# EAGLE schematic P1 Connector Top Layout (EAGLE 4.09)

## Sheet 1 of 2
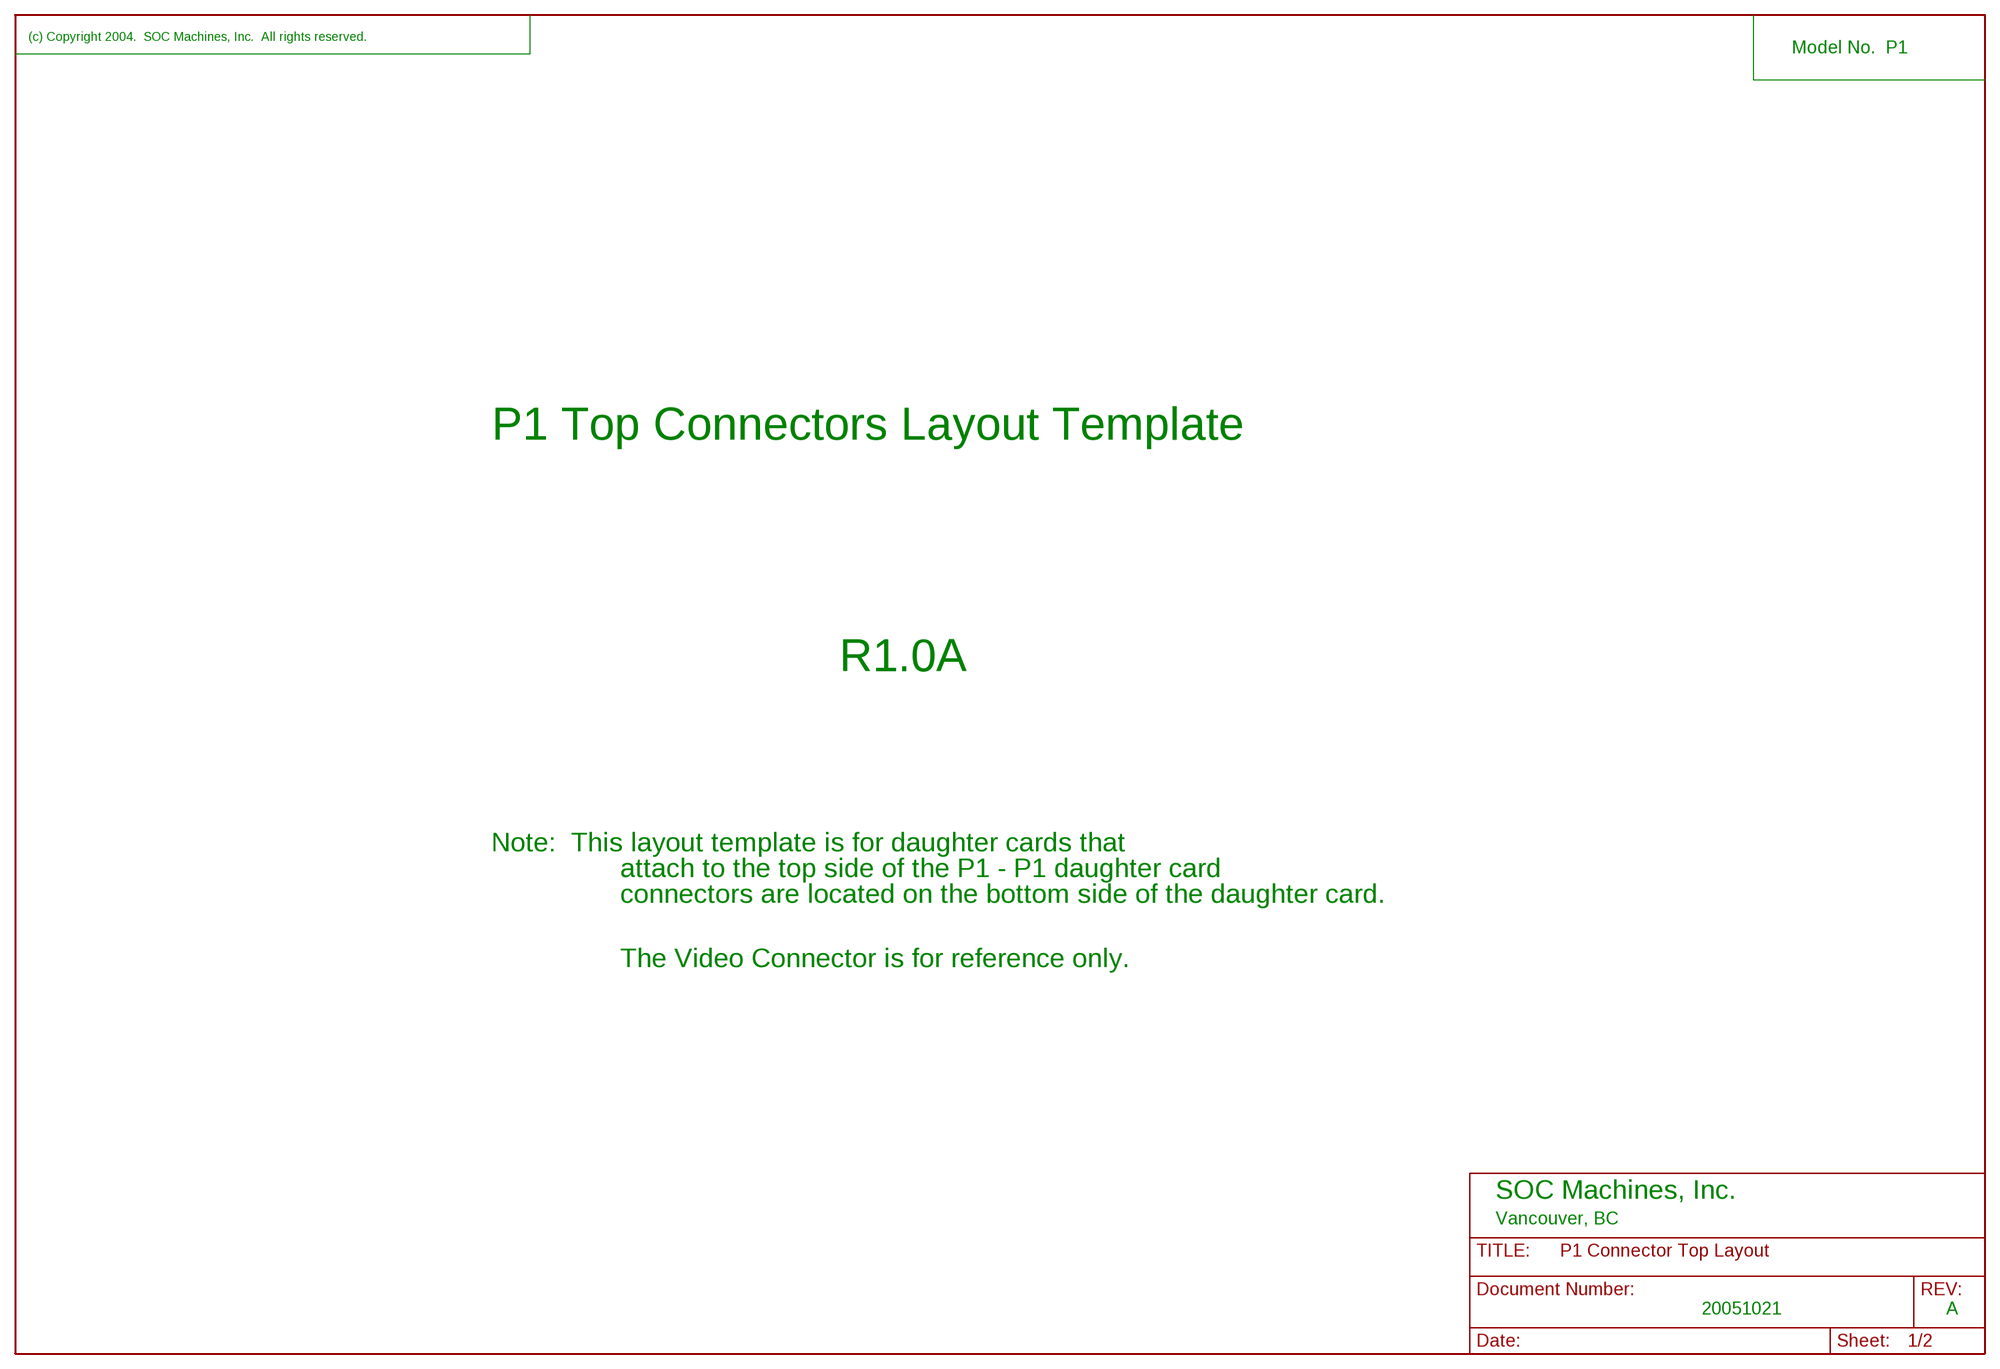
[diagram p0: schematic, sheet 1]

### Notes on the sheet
- (c) Copyright 2004.  SOC Machines, Inc.  All rights reserved.
- Model No.  P1
- P1 Top Connectors Layout Template
- R1.0A
- Note:  This layout template is for daughter cards that
- attach to the top side of the P1 - P1 daughter card
- connectors are located on the bottom side of the daughter card.
- The Video Connector is for reference only.
- SOC Machines, Inc.
- Vancouver, BC
- 20051021 | A

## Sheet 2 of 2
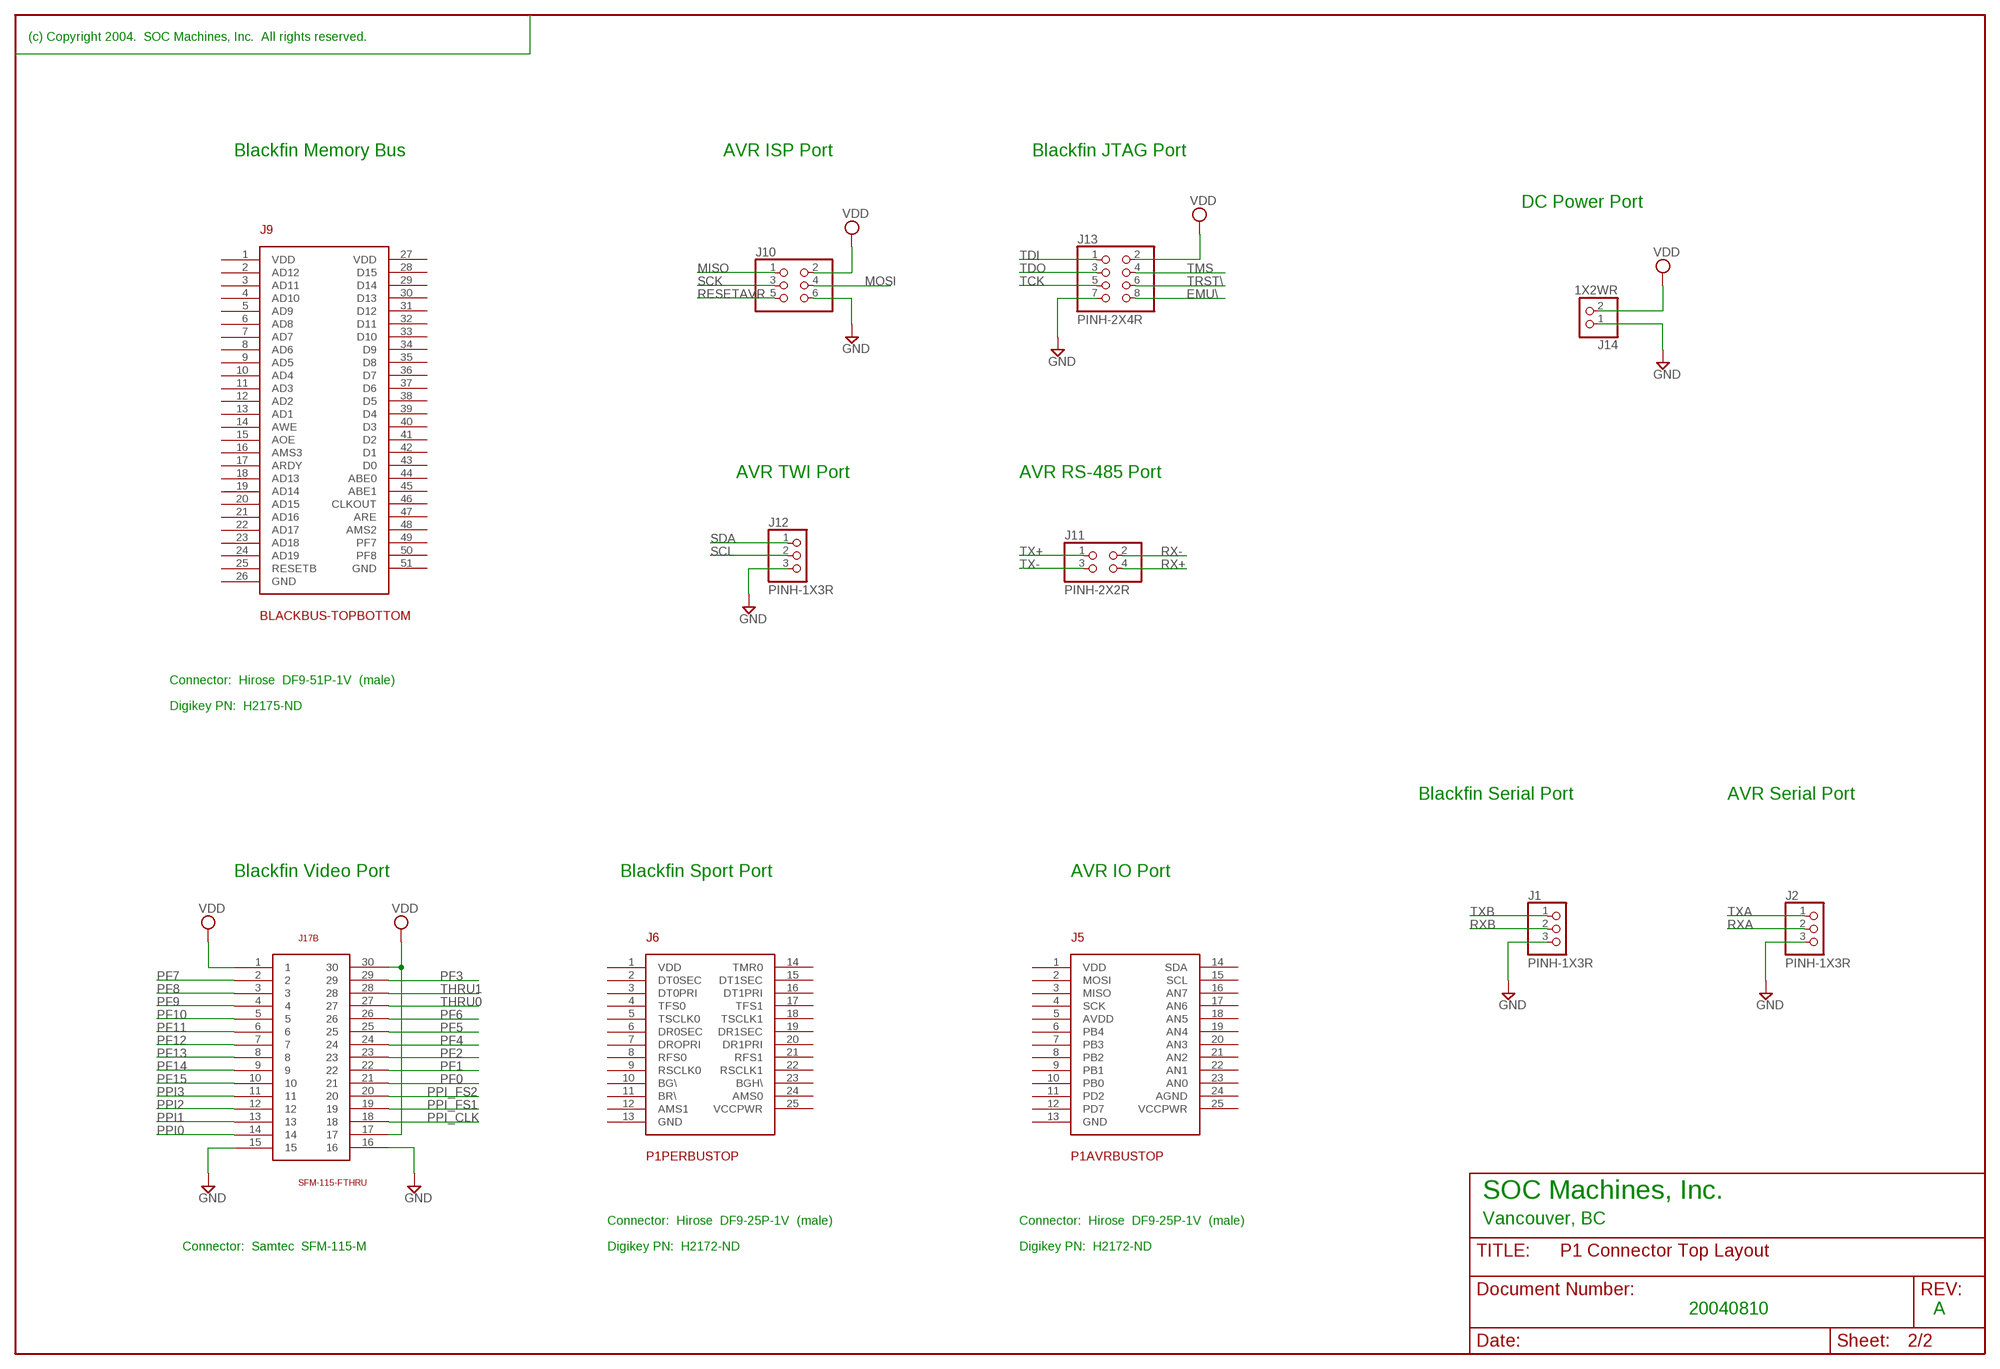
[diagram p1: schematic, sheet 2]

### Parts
J1  PINH-1X3R  [1X3ROUND]
J2  PINH-1X3R  [1X3ROUND]
J5  P1AVRBUSTOP  [DF9-25S]
J6  P1PERBUSTOP  [DF9-25S]
J9  BLACKBUS-TOPBOTTOM  [DF9P-1V]
J10  PINHD-2X3  [2X03]
J11  PINH-2X2R  [2X2ROUND]
J12  PINH-1X3R  [1X3ROUND]
J13  PINH-2X4R  [2X4ROUND]
J14  1X2WR  [1X2WROUND]
J17B  SFM-115-FTHRU  [SFM-115-F]

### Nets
EMU\: J13.8
GND: J1.3 J2.3 J10.6 J12.3 J13.7 J14.1 J17B.15 J17B.16
MISO: J10.1
MOSI: J10.4
PF0: J17B.21
PF1: J17B.22
PF2: J17B.23
PF3: J17B.29
PF4: J17B.24
PF5: J17B.25
PF6: J17B.26
PF7: J17B.2
PF8: J17B.3
PF9: J17B.4
PF10: J17B.5
PF11: J17B.6
PF12: J17B.7
PF13: J17B.8
PF14: J17B.9
PF15: J17B.10
PPI0: J17B.14
PPI1: J17B.13
PPI2: J17B.12
PPI3: J17B.11
PPI_CLK: J17B.18
PPI_FS1: J17B.19
PPI_FS2: J17B.20
RESETAVR: J10.5
RX+: J11.4
RX-: J11.2
RXA: J2.2
RXB: J1.2
SCK: J10.3
SCL: J12.2
SDA: J12.1
TCK: J13.5
TDI: J13.1
TDO: J13.3
THRU0: J17B.27
THRU1: J17B.28
TMS: J13.4
TRST\: J13.6
TX+: J11.1
TX-: J11.3
TXA: J2.1
TXB: J1.1
VDD: J10.2 J13.2 J14.2 J17B.1 J17B.17 J17B.30
Unconnected: J5.2(MOSI) J5.3(MISO) J5.4(SCK) J5.6(PB4) J5.7(PB3) J5.8(PB2) J5.9(PB1) J5.10(PB0) J5.11(PD2) J5.12(PD7) J5.14(SDA) J5.15(SCL) J5.16(AN7) J5.17(AN6) J5.18(AN5) J5.19(AN4) J5.20(AN3) J5.21(AN2) J5.22(AN1) J5.23(AN0) J5.25(VCCPWR) J6.2(DT0SEC) J6.3(DT0PRI) J6.4(TFS0) J6.5(TSCLK0) J6.6(DR0SEC) J6.7(DROPRI) J6.8(RFS0) J6.9(RSCLK0) J6.10(BG\) J6.11(BR\) J6.12(AMS1) J6.14(TMR0) J6.15(DT1SEC) J6.16(DT1PRI) J6.17(TFS1) J6.18(TSCLK1) J6.19(DR1SEC) J6.20(DR1PRI) J6.21(RFS1) J6.22(RSCLK1) J6.23(BGH\) J6.24(AMS0) J9.2(AD12) J9.3(AD11) J9.4(AD10) J9.5(AD9) J9.6(AD8) J9.7(AD7) J9.8(AD6) J9.9(AD5) J9.10(AD4) J9.11(AD3) J9.12(AD2) J9.13(AD1) J9.14(AWE) J9.15(AOE) J9.16(AMS3) J9.17(ARDY) J9.18(AD13) J9.19(AD14) J9.20(AD15) J9.21(AD16) J9.22(AD17) J9.23(AD18) J9.24(AD19) J9.25(RESETB) J9.28(D15) J9.29(D14) J9.30(D13) J9.31(D12) J9.32(D11) J9.33(D10) J9.34(D9) J9.35(D8) J9.36(D7) J9.37(D6) J9.38(D5) J9.39(D4) J9.40(D3) J9.41(D2) J9.42(D1) J9.43(D0) J9.44(ABE0) J9.45(ABE1) J9.46(CLKOUT) J9.47(ARE) J9.48(AMS2) J9.49(PF7) J9.50(PF8)

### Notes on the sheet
- (c) Copyright 2004.  SOC Machines, Inc.  All rights reserved.
- Blackfin Memory Bus | AVR ISP Port | Blackfin JTAG Port
- DC Power Port
- AVR TWI Port | AVR RS-485 Port
- Connector:  Hirose  DF9-51P-1V  (male)
- Digikey PN:  H2175-ND
- Blackfin Serial Port | AVR Serial Port
- Blackfin Video Port | Blackfin Sport Port | AVR IO Port
- SOC Machines, Inc.
- Connector:  Hirose  DF9-25P-1V  (male) | Connector:  Hirose  DF9-25P-1V  (male) | Vancouver, BC
- Connector:  Samtec  SFM-115-M | Digikey PN:  H2172-ND | Digikey PN:  H2172-ND
- 20040810 | A

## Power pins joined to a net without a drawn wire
AGND: J5.24(AGND)
AVDD: J5.5(AVDD)
GND: J5.13(GND) J6.13(GND) J9.26(GND) J9.51(GND)
VCCPWR: J6.25(VCCPWR)
VDD: J5.1(VDD) J6.1(VDD) J9.1(VDD) J9.27(VDD)

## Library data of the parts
J1 J2 J12 = pinhead:PINH-1X3R: 1x3 Pin Head Round
J5 = con-TI DSK 2:P1AVRBUS: P1 AVR Expansion Bus DF9-25 Hirose 1mm Spacing
J6 = con-TI DSK 2:P1PERBUS: P1 Blackfin Peripheral SPORT Bus
J9 = con-TI DSK 2:BLACKBUS-TOP: Blackfin Bus Expansion top connector Hirose DF9
J10 = pinhead:PINHD-2X3: PIN HEADER
J11 = pinhead:PINH-2X2R: Pin Head Jumper 2x2 Round 0.1"
J13 = pinhead:PINH-2X4R
J14 = pinhead:1X2WR
J17B = con-samtec:SFM-115-F: SFM-115-01-S-D-A, 0.05" spacing, female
